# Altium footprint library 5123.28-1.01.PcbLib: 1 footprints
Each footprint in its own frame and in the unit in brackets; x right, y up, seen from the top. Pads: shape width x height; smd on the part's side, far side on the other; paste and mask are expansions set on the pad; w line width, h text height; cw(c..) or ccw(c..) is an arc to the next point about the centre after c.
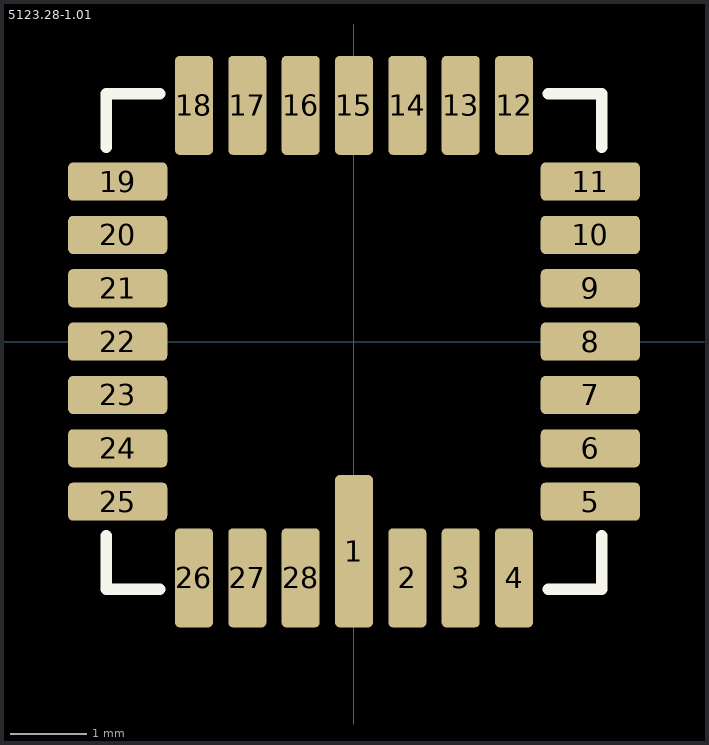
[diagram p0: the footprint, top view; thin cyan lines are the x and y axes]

## 5123.28-1.01 [mm] "5123.28-1.01 chip footprint"
height 2
pads (29):
  rrect25% 0.5x2 smd mask+0.1: 1(0,-2.75)
  rrect25% 0.5x1.3 smd mask+0.1: 2(0.7,-3.1) 3(1.4,-3.1) 4(2.1,-3.1) 12(2.1,3.1) 13(1.4,3.1) 14(0.7,3.1) 15(0,3.1) 16(-0.7,3.1) 17(-1.4,3.1) 18(-2.1,3.1) 26(-2.1,-3.1) 27(-1.4,-3.1) 28(-0.7,-3.1)
  rrect25% 1.3x0.5 smd mask+0.1: 5(3.1,-2.1) 6(3.1,-1.4) 7(3.1,-0.7) 8(3.1,0) 9(3.1,0.7) 10(3.1,1.4) 11(3.1,2.1) 19(-3.1,2.1) 20(-3.1,1.4) 21(-3.1,0.7) 22(-3.1,0) 23(-3.1,-0.7) 24(-3.1,-1.4) 25(-3.1,-2.1)
  round 0.5 on Top Overlay mask+0.1: ""(0,-4.35)
Top Overlay:
  lines w0.15: -3.25,-2.55 -3.25,-3.25 -2.55,-3.25 ; -3.25,2.55 -3.25,3.25 ; -2.55,3.25 -3.25,3.25 ; 2.55,-3.25 3.25,-3.25 3.25,-2.55 ; 2.55,3.25 3.25,3.25 ; 3.25,2.55 3.25,3.25 ; -3.25,3.25 -3.25,3.25 ; 3.25,3.25 3.25,3.25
